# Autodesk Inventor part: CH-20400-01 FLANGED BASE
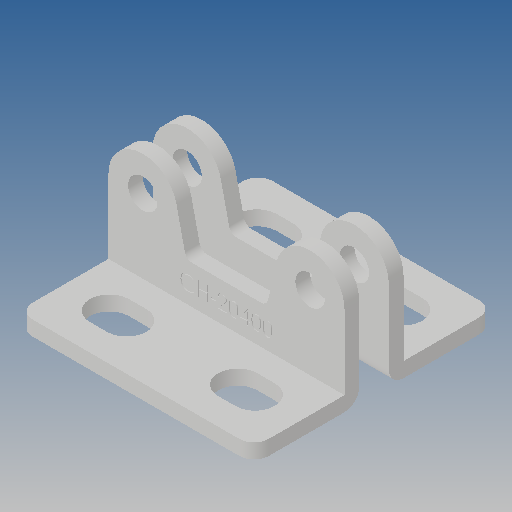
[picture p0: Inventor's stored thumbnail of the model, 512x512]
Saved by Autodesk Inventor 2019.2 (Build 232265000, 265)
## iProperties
Created: 2012-09
Part Number: CH-20400-01 FLANGED BASE
Material: Ogólny
Document SubType Name: Modeling
Designer: CADENGINEERING4
Density: 1 g/cm^3
Appearance: Domyślna
Author: CADENGINEERING4
Revision Number: ÈÎºÎ
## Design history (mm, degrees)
feature "ÇÐ³ý-À­Éì2"
feature "ÇÐ³ý-À­Éì5"
node "Bryła1"
node "Bryła2"
